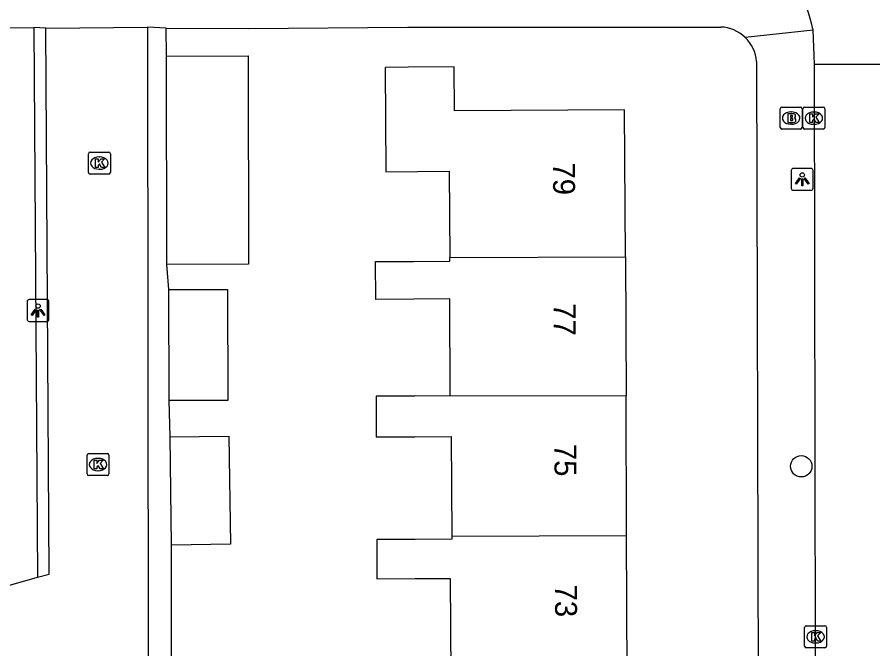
# Model space of a CAD drawing. Extents: x 160732 to 162105, y 387428 to 388479.
# Drawn here: x 161119.44 to 161158.48, y 388296.86 to 388325.67 of the extents above; entities that cross this region are included whole.
import ezdxf

# ---------------------------------------------------------------- set-up
doc = ezdxf.new("R2010")
doc.units = 0
for name, color, linetype in [('IMGEO_Boom', 7, 'Continuous'), ('IMGEO_Brandkraan', 7, 'Continuous'), ('IMGEO_Kolk', 7, 'Continuous'), ('IMGEO_Lichtpunt', 7, 'Continuous'), ('IMGEO_Muur', 7, 'Continuous'), ('IMGEO_Pand', 7, 'Continuous'), ('IMGEO_Pand_nummerreeks', 7, 'Continuous'), ('IMGEO_Rijbaan_lokaal_open', 7, 'Continuous'), ('IMGEO_Voetpad_open', 7, 'Continuous')]:
    doc.layers.add(name, color=color, linetype=linetype)

msp = doc.modelspace()

# ---------------------------------------------------------------- linework, layer by layer
at = {"layer": 'IMGEO_Boom'}
msp.add_circle((161155.215, 388305.189), 0.489, dxfattribs=at)
at = {"layer": 'IMGEO_Brandkraan'}
for p, q in [((161154.329, 388321.563), (161155.181, 388321.563)), ((161154.254, 388320.637), (161154.254, 388321.489)), ((161154.742, 388321.343), (161154.767, 388321.343)), ((161155.255, 388321.489), (161155.255, 388320.637)), ((161154.765, 388320.783), (161154.74, 388320.783)), ((161155.181, 388320.563), (161154.329, 388320.563))]:
    msp.add_line(p, q, dxfattribs=at)
for points in [[(161154.329, 388321.563), (161155.181, 388321.563)], [(161154.254, 388320.637), (161154.254, 388321.489)], [(161154.602, 388321.263), (161154.602, 388320.863), (161154.815, 388320.863)], [(161154.833, 388321.263), (161154.602, 388321.263)], [(161154.781, 388321.182), (161154.727, 388321.182), (161154.727, 388321.106)], [(161154.727, 388321.106), (161154.78, 388321.106)], [(161155.255, 388321.489), (161155.255, 388320.637)], [(161154.789, 388321.03), (161154.727, 388321.03), (161154.727, 388320.949)], [(161154.727, 388320.949), (161154.789, 388320.949)], [(161155.181, 388320.563), (161154.329, 388320.563)]]:
    msp.add_lwpolyline(points, dxfattribs=at)
for centre, radius, start, end in [((161154.331, 388321.487), 0.0765, 91.552, 178.448), ((161154.331, 388321.487), 0.0765, 91.552, 178.448), ((161155.179, 388321.487), 0.0765, 1.552, 88.448), ((161155.179, 388321.487), 0.0765, 1.552, 88.448), ((161154.782, 388321.144), 0.0379, 267.8285, 90.9355), ((161154.837, 388321.118), 0.145, 59.4692, 91.5367), ((161154.862, 388321.165), 0.0922, 285.5137, 58.1501), ((161154.79, 388320.989), 0.0404, 269.8759, 90.5077), ((161154.821, 388321.114), 0.251, 268.6676, 293.5347), ((161154.867, 388320.973), 0.105, 301.3115, 78.989), ((161154.331, 388320.639), 0.0765, 181.552, 268.448), ((161154.331, 388320.639), 0.0765, 181.552, 268.448), ((161155.179, 388320.639), 0.0765, 271.552, 358.448), ((161155.179, 388320.639), 0.0765, 271.552, 358.448)]:
    msp.add_arc(centre, radius, start, end, dxfattribs=at)
for centre, major_axis, ratio, start_param, end_param in [((161154.741, 388321.063), (-0.387, 0.002), 0.722429, 4.712389, 7.853982), ((161154.766, 388321.063), (-0.39, 0.002), 0.717154, 1.570796, 4.712389)]:
    msp.add_ellipse(centre, major_axis=major_axis, ratio=ratio, start_param=start_param, end_param=end_param, dxfattribs=at)
at = {"layer": 'IMGEO_Kolk'}
for p, q in [((161155.365, 388321.56), (161156.217, 388321.56)), ((161155.29, 388320.634), (161155.29, 388321.486)), ((161155.778, 388321.34), (161155.803, 388321.34)), ((161156.291, 388321.486), (161156.291, 388320.634)), ((161155.801, 388320.78), (161155.776, 388320.78)), ((161156.217, 388320.56), (161155.365, 388320.56)), ((161122.697, 388318.585), (161122.697, 388319.437)), ((161122.772, 388319.511), (161123.624, 388319.511)), ((161123.185, 388319.291), (161123.21, 388319.291)), ((161123.698, 388319.437), (161123.698, 388318.585)), ((161123.624, 388318.511), (161122.772, 388318.511)), ((161123.208, 388318.731), (161123.183, 388318.731)), ((161122.634, 388304.84), (161122.634, 388305.692)), ((161122.709, 388305.766), (161123.561, 388305.766)), ((161123.122, 388305.546), (161123.147, 388305.546)), ((161123.635, 388305.692), (161123.635, 388304.84)), ((161123.561, 388304.766), (161122.709, 388304.766)), ((161123.145, 388304.986), (161123.12, 388304.986)), ((161155.37, 388296.987), (161155.37, 388297.839)), ((161155.445, 388297.913), (161156.297, 388297.913)), ((161155.858, 388297.693), (161155.883, 388297.693)), ((161156.371, 388297.839), (161156.371, 388296.987)), ((161156.297, 388296.913), (161155.445, 388296.913)), ((161155.881, 388297.133), (161155.856, 388297.133))]:
    msp.add_line(p, q, dxfattribs=at)
for points in [[(161155.365, 388321.56), (161156.217, 388321.56)], [(161155.29, 388320.634), (161155.29, 388321.486)], [(161155.611, 388321.26), (161155.734, 388321.26), (161155.734, 388321.109), (161155.864, 388321.26), (161156.028, 388321.26), (161155.882, 388321.109), (161156.035, 388320.86), (161155.883, 388320.86), (161155.798, 388321.024), (161155.734, 388320.957), (161155.734, 388320.86), (161155.611, 388320.86), (161155.611, 388321.26)], [(161156.291, 388321.486), (161156.291, 388320.634)], [(161156.217, 388320.56), (161155.365, 388320.56)], [(161122.697, 388318.585), (161122.697, 388319.437)], [(161122.772, 388319.511), (161123.624, 388319.511)], [(161123.018, 388319.211), (161123.141, 388319.211), (161123.141, 388319.06), (161123.271, 388319.211), (161123.435, 388319.211), (161123.289, 388319.06), (161123.442, 388318.811), (161123.29, 388318.811), (161123.205, 388318.975), (161123.141, 388318.908), (161123.141, 388318.811), (161123.018, 388318.811), (161123.018, 388319.211)], [(161123.698, 388319.437), (161123.698, 388318.585)], [(161123.624, 388318.511), (161122.772, 388318.511)], [(161122.634, 388304.84), (161122.634, 388305.692)], [(161122.709, 388305.766), (161123.561, 388305.766)], [(161123.635, 388305.692), (161123.635, 388304.84)], [(161122.955, 388305.466), (161123.078, 388305.466), (161123.078, 388305.315), (161123.208, 388305.466), (161123.372, 388305.466), (161123.226, 388305.315), (161123.379, 388305.066), (161123.227, 388305.066), (161123.142, 388305.23), (161123.078, 388305.163), (161123.078, 388305.066), (161122.955, 388305.066), (161122.955, 388305.466)], [(161123.561, 388304.766), (161122.709, 388304.766)], [(161155.37, 388296.987), (161155.37, 388297.839)], [(161155.445, 388297.913), (161156.297, 388297.913)], [(161156.371, 388297.839), (161156.371, 388296.987)], [(161155.691, 388297.613), (161155.814, 388297.613), (161155.814, 388297.462), (161155.944, 388297.613), (161156.108, 388297.613), (161155.962, 388297.462), (161156.115, 388297.213), (161155.963, 388297.213), (161155.878, 388297.377), (161155.814, 388297.31), (161155.814, 388297.213), (161155.691, 388297.213), (161155.691, 388297.613)], [(161156.297, 388296.913), (161155.445, 388296.913)]]:
    msp.add_lwpolyline(points, dxfattribs=at)
for centre, start, end in [((161155.367, 388321.484), 91.552, 178.448), ((161155.367, 388321.484), 91.552, 178.448), ((161156.215, 388321.484), 1.552, 88.448), ((161156.215, 388321.484), 1.552, 88.448), ((161155.367, 388320.636), 181.552, 268.448), ((161155.367, 388320.636), 181.552, 268.448), ((161156.215, 388320.636), 271.552, 358.448), ((161156.215, 388320.636), 271.552, 358.448), ((161122.774, 388319.435), 91.552, 178.448), ((161122.774, 388319.435), 91.552, 178.448), ((161123.622, 388319.435), 1.552, 88.448), ((161123.622, 388319.435), 1.552, 88.448), ((161122.774, 388318.587), 181.552, 268.448), ((161122.774, 388318.587), 181.552, 268.448), ((161123.622, 388318.587), 271.552, 358.448), ((161123.622, 388318.587), 271.552, 358.448), ((161122.711, 388305.69), 91.552, 178.448), ((161122.711, 388305.69), 91.552, 178.448), ((161123.559, 388305.69), 1.552, 88.448), ((161123.559, 388305.69), 1.552, 88.448), ((161122.711, 388304.842), 181.552, 268.448), ((161122.711, 388304.842), 181.552, 268.448), ((161123.559, 388304.842), 271.552, 358.448), ((161123.559, 388304.842), 271.552, 358.448), ((161155.447, 388297.837), 91.552, 178.448), ((161155.447, 388297.837), 91.552, 178.448), ((161156.295, 388297.837), 1.552, 88.448), ((161156.295, 388297.837), 1.552, 88.448), ((161155.447, 388296.989), 181.552, 268.448), ((161155.447, 388296.989), 181.552, 268.448), ((161156.295, 388296.989), 271.552, 358.448), ((161156.295, 388296.989), 271.552, 358.448)]:
    msp.add_arc(centre, 0.0765, start, end, dxfattribs=at)
for centre, major_axis, ratio, start_param, end_param in [((161155.777, 388321.06), (-0.387, 0.002), 0.722429, 4.712389, 7.853982), ((161155.802, 388321.06), (-0.39, 0.002), 0.717154, 1.570796, 4.712389), ((161123.184, 388319.011), (-0.387, 0.002), 0.722429, 4.712389, 7.853982), ((161123.209, 388319.011), (-0.39, 0.002), 0.717154, 1.570796, 4.712389), ((161123.121, 388305.266), (-0.387, 0.002), 0.722429, 4.712389, 7.853982), ((161123.146, 388305.266), (-0.39, 0.002), 0.717154, 1.570796, 4.712389), ((161155.857, 388297.413), (-0.387, 0.002), 0.722429, 4.712389, 7.853982), ((161155.882, 388297.413), (-0.39, 0.002), 0.717154, 1.570796, 4.712389)]:
    msp.add_ellipse(centre, major_axis=major_axis, ratio=ratio, start_param=start_param, end_param=end_param, dxfattribs=at)
at = {"layer": 'IMGEO_Lichtpunt'}
for p, q in [((161155.663, 388318.768), (161154.855, 388318.768)), ((161155.663, 388318.768), (161154.855, 388318.768)), ((161154.761, 388318.673), (161154.761, 388317.866)), ((161154.761, 388318.673), (161154.761, 388317.866)), ((161155.757, 388317.866), (161155.757, 388318.673)), ((161155.757, 388317.866), (161155.757, 388318.673)), ((161154.855, 388317.772), (161155.663, 388317.772)), ((161154.855, 388317.772), (161155.663, 388317.772)), ((161119.901, 388312.694), (161119.901, 388311.887)), ((161119.901, 388312.694), (161119.901, 388311.887)), ((161120.803, 388312.789), (161119.995, 388312.789)), ((161120.803, 388312.789), (161119.995, 388312.789)), ((161120.897, 388311.887), (161120.897, 388312.694)), ((161120.897, 388311.887), (161120.897, 388312.694)), ((161119.995, 388311.793), (161120.803, 388311.793)), ((161119.995, 388311.793), (161120.803, 388311.793))]:
    msp.add_line(p, q, dxfattribs=at)
for points in [[(161155.135, 388318.337), (161155.174, 388318.309), (161154.986, 388318.047), (161154.948, 388318.074), (161155.135, 388318.337)], [(161155.237, 388318.289), (161155.284, 388318.289), (161155.284, 388317.967), (161155.237, 388317.967), (161155.237, 388318.289)], [(161155.347, 388318.309), (161155.385, 388318.336), (161155.572, 388318.074), (161155.533, 388318.046), (161155.347, 388318.309)], [(161120.275, 388312.358), (161120.314, 388312.33), (161120.126, 388312.068), (161120.088, 388312.095), (161120.275, 388312.358)], [(161120.377, 388312.31), (161120.424, 388312.31), (161120.424, 388311.988), (161120.377, 388311.988), (161120.377, 388312.31)], [(161120.487, 388312.33), (161120.525, 388312.357), (161120.712, 388312.095), (161120.673, 388312.067), (161120.487, 388312.33)]]:
    msp.add_lwpolyline(points, dxfattribs=at)
for centre in [(161155.26, 388318.471), (161120.4, 388312.492)]:
    msp.add_circle(centre, 0.0994, dxfattribs=at)
for centre, start, end in [((161154.855, 388318.673), 90, 180), ((161154.855, 388318.673), 90, 180), ((161155.663, 388318.673), 0, 90), ((161155.663, 388318.673), 0, 90), ((161154.855, 388317.866), 180, 270), ((161154.855, 388317.866), 180, 270), ((161155.663, 388317.866), 270, 0), ((161155.663, 388317.866), 270, 360), ((161119.995, 388312.694), 90, 180), ((161119.995, 388312.694), 90, 180), ((161120.803, 388312.694), 0, 90), ((161120.803, 388312.694), 0, 90), ((161119.995, 388311.887), 180, 270), ((161119.995, 388311.887), 180, 270), ((161120.803, 388311.887), 270, 0), ((161120.803, 388311.887), 270, 360)]:
    msp.add_arc(centre, 0.0946, start, end, dxfattribs=at)
at = {"layer": 'IMGEO_Muur'}
msp.add_lwpolyline([(161129.977, 388325.147), (161137.267, 388325.211)], dxfattribs=at)
at = {"layer": 'IMGEO_Pand'}
for points in [[(161126.257, 388323.889), (161129.987, 388323.895), (161130, 388314.395), (161126.27, 388314.389)], [(161126.27, 388314.389), (161126.257, 388323.889)], [(161147.191, 388314.742), (161147.159, 388321.436), (161139.39, 388321.4), (161139.381, 388323.399), (161137.282, 388323.382), (161136.233, 388323.373), (161136.272, 388318.613), (161139.161, 388318.637), (161139.179, 388314.704)], [(161139.205, 388308.397), (161139.184, 388312.815), (161137.541, 388312.807), (161135.804, 388312.799), (161135.795, 388314.519), (161137.533, 388314.527), (161139.18, 388314.535), (161139.179, 388314.704)], [(161139.179, 388314.704), (161147.191, 388314.742)], [(161147.191, 388314.742), (161147.221, 388308.389)], [(161126.369, 388313.245), (161129.043, 388313.251), (161129.056, 388308.187), (161126.382, 388308.18)], [(161126.382, 388308.18), (161126.369, 388313.245)], [(161139.205, 388308.397), (161137.584, 388308.39), (161135.823, 388308.382), (161135.831, 388306.527), (161137.592, 388306.536), (161139.246, 388306.544), (161139.268, 388301.998)], [(161147.221, 388308.389), (161139.205, 388308.397)], [(161147.251, 388302.036), (161147.221, 388308.389)], [(161126.419, 388306.523), (161129.099, 388306.563), (161129.172, 388301.634), (161126.492, 388301.594)], [(161126.492, 388301.594), (161126.419, 388306.523)], [(161139.268, 388301.998), (161139.269, 388301.859), (161137.597, 388301.852), (161135.851, 388301.845), (161135.859, 388300.059), (161137.605, 388300.068), (161139.202, 388300.076), (161139.223, 388295.645)], [(161139.268, 388301.998), (161147.251, 388302.036)], [(161147.281, 388295.683), (161147.251, 388302.036)]]:
    msp.add_lwpolyline(points, dxfattribs=at)
at = {"layer": 'IMGEO_Rijbaan_lokaal_open'}
for points in [[(161120.378, 388300.126), (161120.905, 388300.275), (161120.757, 388325.168)], [(161120.757, 388325.168), (161125.39, 388325.215)], [(161125.39, 388325.215), (161125.424, 388295.92)], [(161155.814, 388323.521), (161155.76, 388325.065)], [(161155.814, 388323.521), (161160.724, 388323.521)], [(161155.909, 388269.717), (161155.814, 388323.521)], [(161106.78, 388296.233), (161112.428, 388297.937), (161113.879, 388298.284), (161120.378, 388300.126)]]:
    msp.add_lwpolyline(points, dxfattribs=at)
msp.add_arc((161149.354, 388323.752), 6.539, 11.5825, 86.8101, dxfattribs=at)
at = {"layer": 'IMGEO_Voetpad_open'}
for points in [[(161074.262, 388323.039), (161074.263, 388325.112), (161120.205, 388325.197)], [(161120.205, 388325.197), (161120.378, 388300.126)], [(161120.757, 388325.168), (161120.205, 388325.197)], [(161126.249, 388325.162), (161125.39, 388325.215)], [(161126.249, 388325.162), (161129.977, 388325.147), (161137.267, 388325.211), (161151.542, 388325.215)], [(161126.257, 388323.889), (161126.249, 388325.162)], [(161155.76, 388325.065), (161152.658, 388324.74)], [(161153.177, 388323.643), (161153.348, 388261.595), (161153.537, 388261.595), (161153.578, 388254.587), (161153.367, 388254.587)], [(161126.369, 388313.245), (161126.27, 388314.389)], [(161126.419, 388306.523), (161126.382, 388308.18)], [(161126.494, 388295.922), (161126.492, 388301.594)]]:
    msp.add_lwpolyline(points, dxfattribs=at)
for centre, radius, start, end in [((161151.476, 388323.512), 1.704, 46.0999, 87.7882), ((161151.471, 388323.507), 1.712, 4.557, 46.0814)]:
    msp.add_arc(centre, radius, start, end, dxfattribs=at)

# ---------------------------------------------------------------- texts
at = {"layer": 'IMGEO_Pand_nummerreeks'}
for s, p in [('79', (161143.891, 388319.039)), ('77', (161143.922, 388312.624)), ('75', (161143.952, 388306.21)), ('73', (161143.982, 388299.795))]:
    msp.add_text(s, height=1, rotation=270.2713, dxfattribs=at).set_placement(p)

doc.saveas('drawing.dxf')
